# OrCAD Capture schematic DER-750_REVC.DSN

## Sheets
1 PAGE2: size A
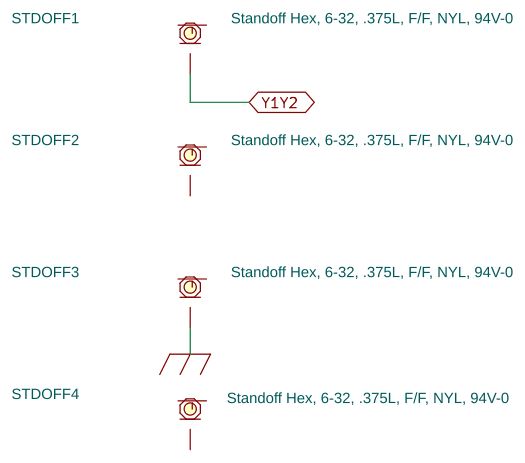
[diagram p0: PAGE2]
2 PAGE1: size Custom
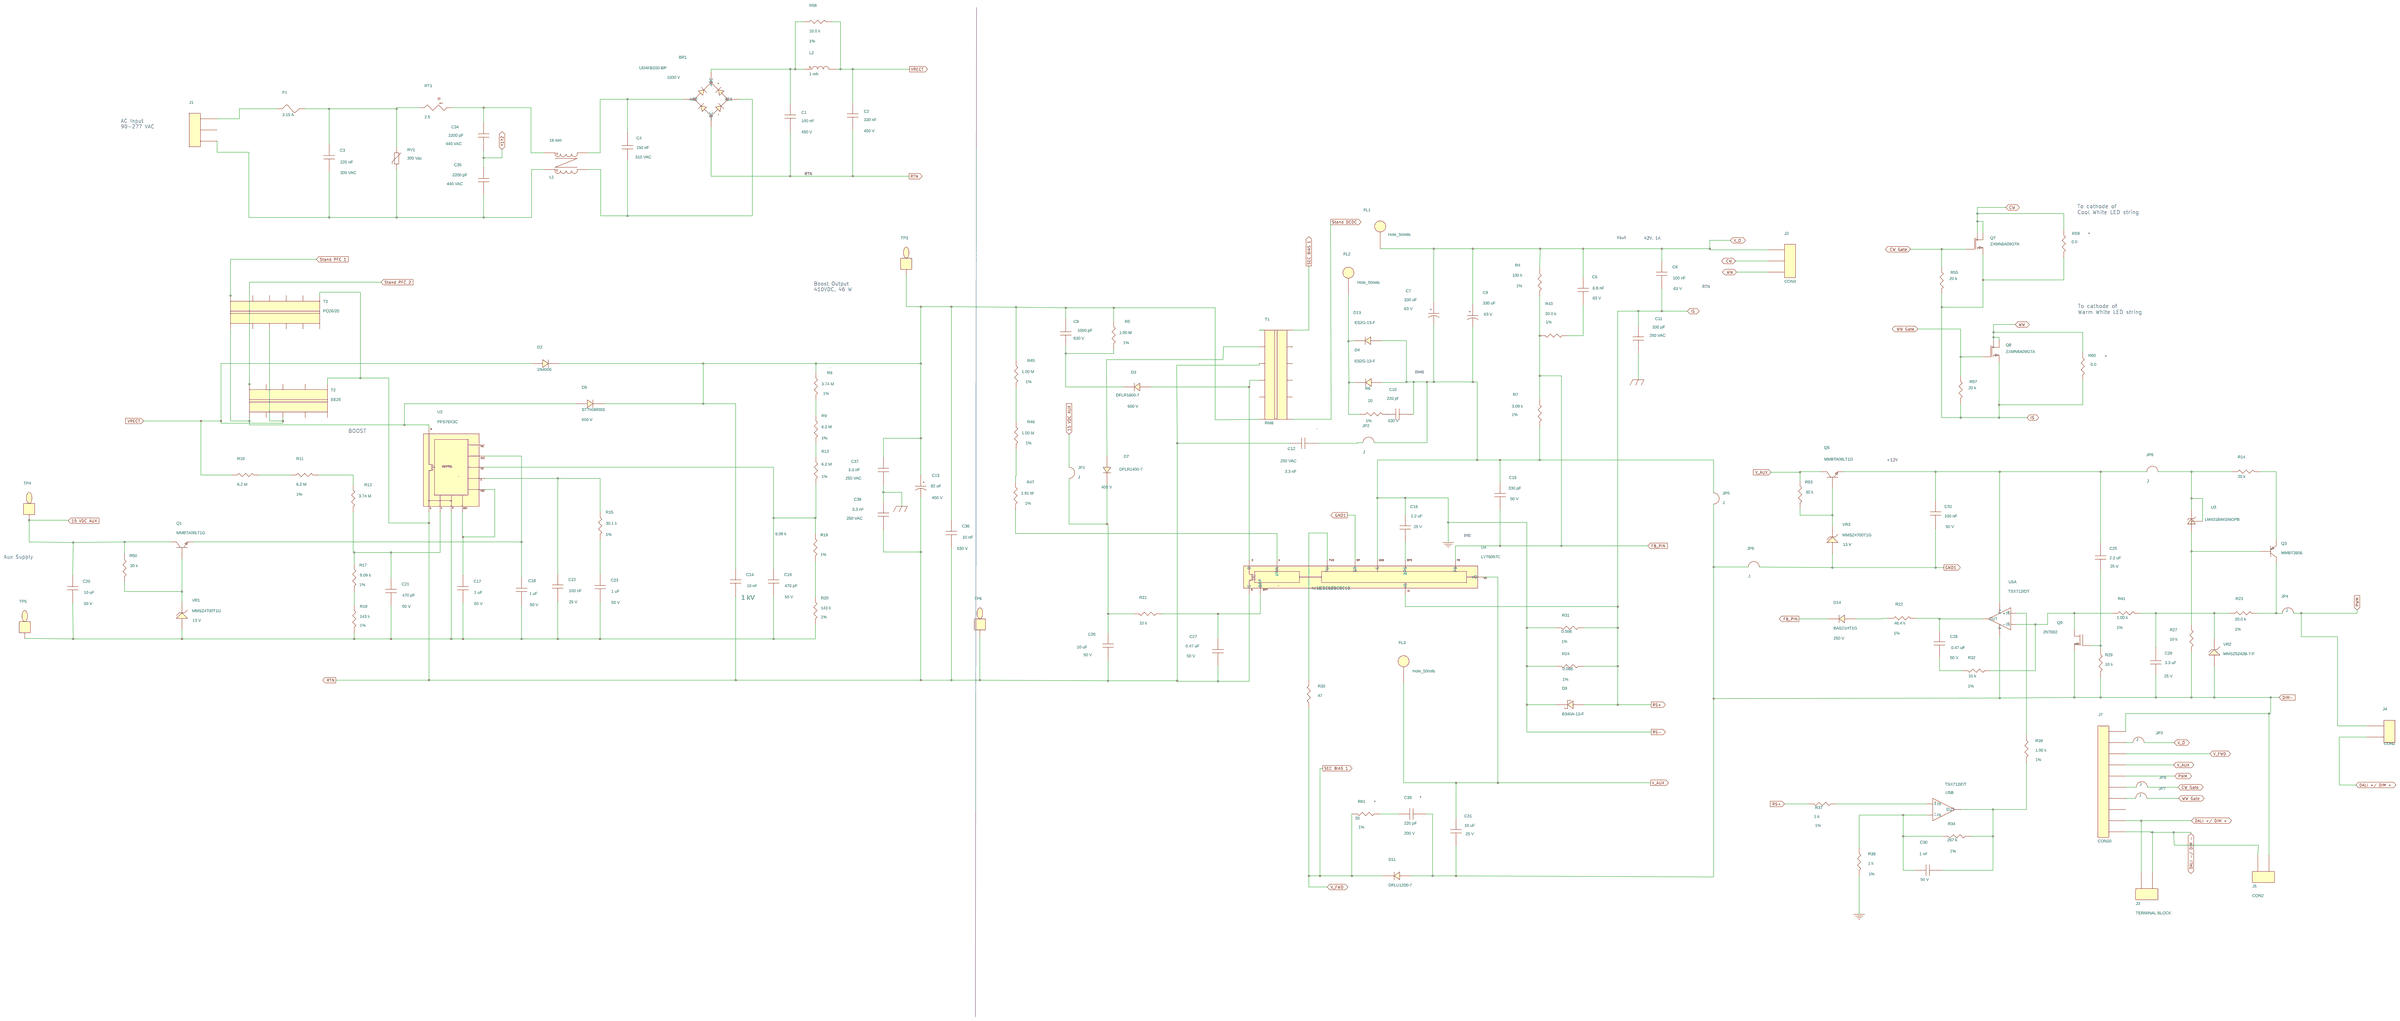
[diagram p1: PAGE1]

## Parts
sheet PAGE1
BR1  UD4KB100-BP  [pidaxbridgeD3K]
C1  100 nF  [pi_np_xcap_rad512x197x395d040]
C2  330 nF  [pi_np_caprad512x299ls394d040]
C3  220 nF  [pinpxcaprad710x315590046]
C4  150 nF  [pinpxcaprad720x240590040]
C5  6.8 nF  [pismc0603]
C6  100 nF  [pismc1206]
C7  330 uF  [pipolcapcyld400ls200040]
C8  330 uF  [pipolcapcyld400ls200040]
C9  1000 pF  [pismc1206]
C10  220 pf  [pismc1206]
C11  330 pF  [pinpycaprad470x210ls380040]
C12  3.3 nF  [pinpycaprad540x290ls400040]
C13  82 uF  [pipolcapclyd710ls300040]
C14  10 nF  [pi_np_cap250x200ls170d030]
C15  330 pF  [pismc0603]
C16  2.2 uF  [pismc1206]
C17  1 uF  [pismc0805]
C18  1 uF  [pismc0805]
C19  470 pF  [pismc0805]
C20  10 uF  [pismc1206]
C21  470 pF  [pismc0805]
C22  100 nF  [pismc0805]
C23  1 uF  [pismc0805]
C25  2.2 uF  [pismc0805]
C26  10 uF  [pismc1206]
C27  0.47 uF  [pismc0805]
C28  0.47 uF  [pismc0805]
C29  3.3 uF  [pismc0805]
C30  1 nF  [pismc0805]
C31  10 uF  [pismc1206]
C32  100 nF  [pismc0805]
C34  2200 pF  [pinpcaprad394x275394030]
C35  2200 pF  [pinpcaprad394x275394030]
C36  10 nF  [pismc1206]
C37  3.3 nF  [pinpycaprad540x290ls400040]
C38  3.3 nF  [pinpycaprad540x290ls400040]
C39  220 pF  [pismc0805]
D2  1N4006  [pidv200x110x040do41]
D3  DFLR1600-7  [pismddflr120012]
D4  ES2G-13-F  [pismdo214aa12]
D5  STTH3R06S  [pismdo214ab12]
D7  DFLR1400-7  [pismddflr120012]
D9  B340A-13-F  [pismdo214ac12]
D11  DFLU1200-7  [pismddflr120012]
D13  ES2G-13-F  [pismdo214aa12]
D14  BAS21HT1G  [pismsod323]
F1  3.15 A  [pi_rst_microfuse]
FL1  Hole_50mils  [pi_hole_50mil]
FL2  Hole_50mils  [pi_hole_50mil]
FL3  Hole_50mils  [pi_hole_50mil]
J1  TERMINAL BLOCK  [pi_term_block_3pin]
J2  CON3  [pi_hdr_3pin_phoenix_3p5ls100d]
J3  TERMINAL BLOCK  [pi_term_block_2pin_ls200]
J4  CON2  [pimolex2kkheader]
J5  CON2  [pimolex2kkheader]
J7  CON10  [pi_molex_10]
JP1  J  [pi_jumper200]
JP2  J  [pi_jumper300]
JP3  J  [pi_jumper300]
JP4  J  [pi_jumper300]
JP5  J  [pi_jumper1000]
JP6  J  [pi_jumper300]
JP7  J  [pi_jumper300]
JP8  J  [pi_jumper300]
JP9  J  [pi_jumper300]
L1  18 mH  [pi_ind_4p_690x512ls300x200d055]
L2  1 mh  [pi_choke_RL5480-5_d2]
Q1  MMBTA06LT1G  [pismsot23123_1]
Q3  MMBT3906  [pismsot23123_1]
Q5  2N7002  [pismsot23123_1]
Q6  MMBTA06LT1G  [pismsot23123_1]
Q7  ZXMN6A09GTA  [pismsot2231234]
Q8  ZXMN6A09GTA  [pismsot2231234]
R4  100 k  [pismr0805]
R5  1.00 M  [pismr1206]
R6  20  [pismr1206]
R7  3.09 k  [pismr0603]
R8  3.74 M  [pi14wvresd100ls100d030]
R9  6.2 M  [pismr1206]
R10  6.2 M  [pi14wvresd100ls100d030]
R11  6.2 M  [pismr1206]
R12  6.2 M  [pismr1206]
R13  3.74 M  [pismr1206]
R14  20 k  [pismr0603]
R15  30.1 k  [pismr0805]
R17  9.09 k  [pismr0805]
R18  143 k  [pismr0805]
R19  9.09 k  [pismr0805]
R20  143 k  [pismr0805]
R21  10 k  [pismr1206]
R22  46.4 k  [pismr1206]
R23  20.0 k  [pismr0805]
R24  0.068  [pismr1206]
R27  10 k  [pismr0805]
R29  10 k  [pismr0805]
R30  47  [pismr1206]
R31  0.068  [pismr1206]
R32  10 k  [pismr0805]
R34  267 k  [pismr0805]
R37  1 k  [pi14wvresd100ls100d030]
R38  1 k  [pi14wvresd100ls100d030]
R39  1.00 k  [pismr0805]
R41  1.00 k  [pismr0805]
R43  20.0 k  [pismr0805]
R45  1.00 M  [pismr1206]
R46  1.00 M  [pismr1206]
R47  1.91 M  [pismr1206]
R50  30 k  [pismr0805]
R53  30 k  [pismr0805]
R55  20 k  [pismr0805]
R57  20 k  [pismr0805]
R58  10.0 k  [pismr1206]
R59  0.0  [pismr0805]
R60  0.0  [pismr0805]
R61  20  [pismr1206]
RT1  2.5  [pi_rad150x300ls200d030]
RV1  300 Vac  [pidisc350x225ls240x140040]
T1  RM8  [pi_bobbin_rm8_12p]
T2  EE25  [pi_bobbin_ee25_10p]
T3  PQ26/20  [pi_bobbin_bpq26_20_12p]
TP3  CON1  [pitpkeystone125x125]
TP4  CON1  [pitpkeystone125x125]
TP5  CON1  [pitpkeystone125x125]
TP6  CON1  [pitpkeystone125x125]
U2  PFS76X3C  [PI_IC_INSOP24B]
U3  LM431BIM3/NOPB  [pismsot23123]
U4  LYT6067C  [pi_ic_insop_24d]
U5  TSX712IDT  [pismso8]  (sections A,B)
VR1  MMSZ4700T1G  [pi_sm_sod-123_12]
VR2  MMSZ5242B-7-F  [pi_sm_sod-123_12]
VR3  MMSZ4700T1G  [pi_sm_sod-123_12]
sheet PAGE2
STDOFF1  Standoff Hex, 6-32, .375L, F/F, NYL, 94V-0  [pi_standoff_6_32]
STDOFF2  Standoff Hex, 6-32, .375L, F/F, NYL, 94V-0  [pi_standoff_6_32]
STDOFF3  Standoff Hex, 6-32, .375L, F/F, NYL, 94V-0  [pi_standoff_6_32]
STDOFF4  Standoff Hex, 6-32, .375L, F/F, NYL, 94V-0  [pi_standoff_6_32]

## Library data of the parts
BR1 = DISCRETE_BRIDGE_+~~-: ALT_SYMBOLS: pidaxbridgeD3K_horz; Disp_Voltage: 1000 V; FPLIST: pidaxbridgeD3K,pidaxbridgeD3K_horz; Part Number: 15-01213-00
C1 = CAP_NP: Disp_Voltage: 450 V; Part Number: 20-01140-00; Voltage: 450 V
C2 = CAP_NP: ALT_SYMBOLS: pi_np_caprad512x299ls394d040_h; Disp_Voltage: 450 V; FPLIST: pi_np_caprad512x299ls394d040,pi_np_caprad512x299ls394d040_h; Part Number: 20-00973-00; Voltage: 450 V
C3 = CAP_NP: Disp_Voltage: 300 VAC; Part Number: 20-00730-00; Voltage: 300 VAC
C4 = CAP_NP: Disp_Voltage: 310 VAC; Part Number: 20-01052-00; Voltage: 310 VAC
C5 = CAP_NP: Disp_Voltage: 63 V; Part Number: 20-08888-00; Voltage: 50 V
C6 = CAP_NP: Disp_Voltage: 63 V; Part Number: 20-08738-00; Voltage: 50 V
C7 C8 = CAP_POL: COMPGROUP: 3; Disp_Voltage: 63 V; FPLIST: pipolcapcyld400ls200040,pipolcapcylD10mLS5mH22m040H; Part Number: 20-09012-00; Voltage: 50 V
C9 = CAP_NP: Disp_Voltage: 630 V; Part Number: 20-08616-00; Voltage: 630 V
C10 = CAP_NP: Disp_Voltage: 630 V; PCB Editor PCBFP: pismc0603; Part Number: 20-01036-00; Voltage: 630 V
C11 = CAP_NP: Disp_Voltage: 250 VAC; Part Number: 20-00373-00; Voltage: 250 VAC
C12 = CAP_NP: ALT_SYMBOLS: pinpycaprad540x290ls400040h; COMPGROUP: 3; Disp_Voltage: 250 VAC; FPLIST: pinpycaprad540x290ls400040,pinpycaprad540x290ls400040h; Part Number: 20-00377-00; Voltage: 250 VAC
C13 = CAP_POL: ALT_SYMBOLS: pi_cap_cly_d710_ls300_040_1035h; Disp_Voltage: 450 V; FPLIST: pipolcapclyd710ls300040,pi_cap_cly_d710_ls300_040_1035h; Part Number: 20-00523-00; Voltage: 450 V
C14 = CAP_NP: Disp_Voltage: 1 kV; Part Number: 20-00894-00; Voltage: 1 kV
C15 = CAP_NP: Disp_Voltage: 50 V; Part Number: 20-08676-00; Voltage: 50 V
C16 = CAP_NP: Disp_Voltage: 25 V; Part Number: 20-01034-00; Voltage: 25 V
C17 C18 C23 = CAP_NP: Disp_Voltage: 50 V; Part Number: 20-09156-00; Voltage: 50 V
C19 C21 = CAP_NP: Disp_Voltage: 50 V; Part Number: 20-00205-00; Voltage: 50 V
C20 C26 = CAP_NP: ALT_SYMBOLS: pismc1206_1; Disp_Voltage: 50 V; FPLIST: pismc1206,pismc1206_1; Part Number: 20-08995-00; Voltage: 50 V
C22 = CAP_NP: Disp_Voltage: 25 V; Part Number: 20-08599-00; Voltage: 25 V
C25 = CAP_NP: Disp_Voltage: 25 V; Part Number: 20-08603-00; Voltage: 25 V
C27 C28 = CAP_NP: Disp_Voltage: 50 V; Part Number: 20-09197-00; Voltage: 50 V
C29 = CAP_NP: Disp_Voltage: 25 V; Part Number: 20-01041-00; Voltage: 25 V
C30 = CAP_NP: Disp_Voltage: 50 V; Part Number: 20-08750-00; Voltage: 50 V
C31 = CAP_NP: Disp_Voltage: 25 V; Part Number: 20-08608-00; Voltage: 25 V
C32 = CAP_NP: Disp_Voltage: 50 V; Part Number: 20-00904-00; Voltage: 50 V
C34 C35 = CAP_NP: ALT_SYMBOLS: pinpycaprad500x220ls400040; Disp_Voltage: 440 VAC; FPLIST: pinpcaprad394x275394030,pinpycaprad500x220ls400040; Part Number: 20-09196-00; Voltage: 440 VAC
C36 = CAP_NP: Disp_Voltage: 630 V; Part Number: 20-00939-00; Voltage: 630 V
C37 C38 = CAP_NP: ALT_SYMBOLS: pinpycaprad540x290ls400040h; Disp_Voltage: 250 VAC; FPLIST: pinpycaprad540x290ls400040,pinpycaprad540x290ls400040h; Part Number: 20-00377-00; Voltage: 250 VAC
C39 = CAP_NP: Disp_Voltage: 200 V; Part Number: 20-09094-00; Voltage: 200 V
D2 = DIODE: ALT_SYMBOLS: pidax475x125040do41,pidv200x110x040do41wbead,pidax390x125040do41; FPLIST: pidv200x110x040do41,pidax475x125040do41,pidv200x110x040do41wbead,pidax390x125040do41; Part Number: 15-00629-00
D3 = DIODE: Disp_Voltage: 600 V; Part Number: 15-00826-00
D4 D13 = DIODE: Part Number: 15-01075-00
D5 = DIODE: Disp_Voltage: 600 V; Part Number: 15-00827-00
D7 = DIODE: COMPGROUP: 1; Disp_Voltage: 400 V; Part Number: 15-01310-00
D9 = DIODE_SCHOTTKY: Part Number: 15-01172-00
D11 = DIODE: Part Number: 15-01043-00
D14 = DIODE: ALT_SYMBOLS: pismsod323_1; Disp_Voltage: 250 V; FPLIST: pismsod323,pismsod323_1; Part Number: 15-01247-00
F1 = FUSE: ALT_SYMBOLS: pirstmicrofusehoz; FPLIST: pi_rst_microfuse,pirstmicrofusehoz; Part Number: 40-00020-00
FL1-FL3 = FlyingLead: Part Number: 35-00283-00
J1 = CON3: Part Number: 35-00175-00
J2 = CON3: Part Number: 35-00463-00
J3 = CON2: Part Number: 35-00277-00
J4 J5 = CON2: Part Number: 35-00077-00
J7 = CON10: Part Number: 35-00014-00
JP1 = JUMPER_1: Part Number: 65-00119-00
JP2-JP4 JP6-JP9 = JUMPER_1: Part Number: 65-00120-00
JP5 = JUMPER_1: Part Number: 65-00127-00
L1 = CMC__4P_12_43: ALT_SYMBOLS: pi_4p_700x400d055_horiz; FPLIST: pi_ind_4p_690x512ls300x200d055,pi_4p_700x400d055_horiz; Part Number: 30-04100-00
L2 = INDUCTOR_dot2: ALT_SYMBOLS: pi_choke_RL5480-5H_d2; FPLIST: pi_choke_RL5480-5_d2,pi_choke_RL5480-5H_d2; Part Number: 30-00318-00
Q1 Q6 = NPN_BEC: Part Number: 55-00072-00
Q3 = PNP_BEC: Part Number: 55-00049-00
Q5 = FET_N_GSD: Part Number: 50-00103-00
Q7 Q8 = FET_N_GDSD: Part Number: 50-00248-00
R4 = R: Disp_Tol: 1%; Part Number: 05-00780-00
R5 R45 R46 = R: Disp_Tol: 1%; Part Number: 05-03149-00
R6 R61 = R: Disp_Tol: 1%; Part Number: 05-00030-00
R7 = R: Disp_Tol: 1%; Part Number: 05-01125-00
R8 = R: ALT_SYMBOLS: pi14wvresd100ls200d030,pi14wresd100ls400d030,pi14wresd100ls500d030; Disp_Tol: 1%; FPLIST: pi14wvresd100ls100d030,pi14wvresd100ls200d030,pi14wresd100ls400d030,pi14wresd100ls500d030; Part Number: 05-05566-00
R9 R11 R12 = R: Disp_Tol: 1%; Part Number: 05-05567-00
R10 = R: ALT_SYMBOLS: pi14wvresd100ls200d030,pi14wresd100ls400d030,pi14wresd100ls500d030; FPLIST: pi14wvresd100ls100d030,pi14wvresd100ls200d030,pi14wresd100ls400d030,pi14wresd100ls500d030; Part Number: 05-03122-00
R13 = R: Part Number: 05-05572-00
R14 = R: Part Number: 05-01719-00
R15 = R: Disp_Tol: 1%; Part Number: 05-00730-00
R17 R19 = R: Disp_Tol: 1%; Part Number: 05-03397-00
R18 R20 = R: Disp_Tol: 1%; Part Number: 05-00795-00
R21 = R: Part Number: 05-01376-00
R22 = R: Disp_Tol: 1%; Part Number: 05-00353-00
R23 R43 = R: Disp_Tol: 1%; Part Number: 05-00713-00
R24 R31 = R: Disp_Tol: 1%; Part Number: 05-06499-00
R27 R29 = R: Part Number: 05-01543-00
R30 = R: Part Number: 05-01320-00
R32 = R: Disp_Tol: 1%; Part Number: 05-00684-00
R34 = R: Disp_Tol: 1%; Part Number: 05-00821-00
R37 R38 = R: ALT_SYMBOLS: pi14wvresd100ls200d030,pi14wresd100ls400d030,pi14wresd100ls500d030; Disp_Tol: 1%; FPLIST: pi14wvresd100ls100d030,pi14wvresd100ls200d030,pi14wresd100ls400d030,pi14wresd100ls500d030; Part Number: 05-01976-00
R39 R41 = R: Disp_Tol: 1%; Part Number: 05-03310-00
R47 = R: Disp_Tol: 1%; Part Number: 05-05409-00
R50 R53 = R: Part Number: 05-01554-00
R55 R57 = R: Part Number: 05-01550-00
R58 = R: Disp_Tol: 1%; Part Number: 05-00289-00
R59 R60 = R: ALT_SYMBOLS: pismr0805_1; FPLIST: pismr0805,pismr0805_1; Part Number: 05-03159-00
RT1 = THERMISTOR: ALT_SYMBOLS: pirad400x300ls200040_h; FPLIST: pi_rad150x300ls200d030,pirad400x300ls200040_h; Part Number: 90-00040-00
RV1 = VARISTOR: Part Number: 85-00031-00
T1 = BRM8_12P_GENERIC: ALT_SYMBOLS: pi_bobbin_rm8_12p_inline_clp; FPLIST: pi_bobbin_rm8_12p,pi_bobbin_rm8_12p_inline_clp; Part Number: 25-00041-00
T2 = BEE25_10P_GENERIC: Part Number: 25-00015-00
T3 = BPQ26_20_12P_GENERIC: Part Number: 25-00025-00
TP3 TP4 = TESTPOINT: Part Number: 35-00042-00
TP5 TP6 = TESTPOINT: Part Number: 35-00044-00
U2 = DEV_HiperPFS7_inSOP: Part Number: 10-01067-00
U3 = TL431_SOT-23_CAR: Part Number: 45-00232-00
U4 = LYT6: Part Number: 10-01080-00
U5 = TSX712IDT: Part Number: 45-00514-00
VR1 VR3 = DIODE_ZENER: Disp_Voltage: 13 V; Part Number: 15-01046-00
VR2 = DIODE_ZENER: Part Number: 15-01090-00
STDOFF1-STDOFF4 = STDOFF_HEX_6-32: Part Number: 76-00032-00

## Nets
GND: C7.2 C8.2 C10.2 C15.1 C16.1 D4.2 D9.1 D13.2 JP2.2 JP5.1 R7.2 R24.2 R31.2 R38.2 U4.2(G)
GND1: C32.2 JP6.2 U4.5(SR) VR3.2
GND_EARTH: C11.2 C37.2 C38.1 STDOFF3.1
15 VDC AUX: C20.1 JP1.1 Q1.3(COLLECTOR) R50.1 TP4.1
CW: J2.2 Q7.2(D1) Q7.4(D2) R59.1
CW Gate: JP9.2 Q7.1(G) R55.1
DALI +/ DIM +: J3.2 J4.2 J7.2
DALI -/ DIM -: J3.1 J5.2 J7.1
DIM-: C29.1 C31.2 C39.2 D11.2 J5.1 J7.10 JP5.2 JP6.1 Q5.2(S) R27.2 R29.2 U5.4(V-) VR2.2
FB_PIN: C15.2 D14.1 R4.2 R7.1 R43.2 U4.3(FB)
IS: C6.2 C11.1 D9.2 Q7.3(S) Q8.3(S) R24.1 R31.1 R37.2 R55.2 R57.2 R59.2 R60.2 U4.1(IS)
NC8: U4.8(NC8)
NC9: U2.9(NC9) U4.9(NC9)
NC10: U2.10(NC10) U4.10(NC10)
NC11: U2.11(NC11) U4.11(NC11)
NC12: U2.12(NC12) U4.12(NC12)
NC13: U2.13(NC13)
NC14: U2.14(NC14)
NC15: U2.15(NC15) U4.15(nc15)
PWM: J4.1 J7.6 JP4.2
RTN: BR1.4(-DC) C1.2 C2.2 C12.1 C13.2 C14.2 C26.2 C27.2 C36.2 C38.2 T1.4 T2.6 T3.7 TP6.1 U2.24(S) U4.16(S)
SEC BIAS 1: D11.1 J7.8 R30.1 R61.2 T1.7
Stand DCDC: T1.12
Stand PFC 1: T3.12
Stand PFC 2: T2.10
V_AUX: C31.1 FL3.1 J7.7 Q6.3(COLLECTOR) R53.1 U4.6(VO)
V_O: C5.1 C6.1 C7.1 C8.1 FL1.1 J2.1 JP3.2 R4.1
VRECT: C2.1 D2.2 L2.1 R10.1 R58.2 T2.3 T3.3
WW: J2.3 Q8.2(D1) Q8.4(D2) R60.1
WW Gate: JP7.2 Q8.1(G) R57.1
Y1Y2: C34.2 C35.1 STDOFF1.1
N11473952: BR1.1(+DC) C1.1 L2.2 R58.1
N11474046: F1.1 J1.3
N11474074: C3.1 F1.2 RT1.1 RV1.1
N11474232: C3.2 C35.2 J1.1 L1.4 RV1.2
N11475153: C9.2 C13.1 C14.1 C36.1 C37.1 D2.1 D5.1 R5.1 R8.1 R45.1 T1.1 TP3.1
N11476179: D5.2 T2.1 T3.1 U2.16(D)
N11479125: C18.1 Q1.2(EMITTER) U2.1(VCC)
N11479543: C19.1 R12.1 R19.1 U2.6(FB)
N11479547: C22.1 R15.1 U2.5(C)
N11479611: C23.1 R15.2
N11479651: C17.2 C18.2 C19.2 C20.2 C21.2 C22.2 C23.2 R18.2 R20.2 TP5.1 U2.2(G) VR1.2
N11480020: C21.1 R13.2 R17.1 U2.4(V)
N11480864: R10.2 R11.1
N11480868: R11.2 R13.1
N11481429: C17.1 U2.3(REF) U2.8(PGT)
N11482333: R9.2 R12.2
N11498937: D4.1 D13.1 FL2.1 R6.2
N11498945: C9.1 D3.1 R5.2
N11499175: C10.1 R6.1
N11499187: D7.2 T1.5
N11499225: D3.2 T1.3 U4.24(D)
N11499449: C26.1 D7.1 JP1.2 R21.1
N11499609: R30.2 U4.7(FW)
N11499647: R47.2 U4.13(VPIN)
N11499655: C16.2 U4.4(BPS)
N11499799: C27.1 R21.2 U4.14(BPP)
N11939314: R19.2 R20.1
N11939723: R17.2 R18.1
N11948429: R45.2 R46.1
N11948437: R46.2 R47.1
N12022540: C12.2 JP2.1
N12100407: C25.2 C32.1 JP8.1 Q6.2(EMITTER) U5.8(V+)
N12100435: JP8.2 R14.1 U3.1(C) U3.3(VREF)
N12100443: Q3.2(EMITTER) R14.2
N12100467: Q6.1(BASE) R53.2 VR3.1
N12100553: Q3.1(BASE) R27.1 U3.2(A)
N12100613: JP4.1 Q3.3(COLLECTOR) R23.2
N12100617: C25.1 Q5.1(G) R29.1
N12100771: R39.1 U5.3(+IN)
N12100779: Q5.3(D) R32.1 R41.1 U5.2(-IN)
N12100795: C29.2 R23.1 R41.2 VR2.1
N12100835: D14.2 R22.1
N12100839: C28.1 R22.2 U5.1(OUT)
N12100987: C28.2 R32.2
N12101111: C30.2 R34.1 R39.2 U5.7(OUT)
N12101185: R37.1 U5.5(+IN)
N12101201: C30.1 R34.2 R38.1 U5.6(-IN)
N12102647: Q1.1(BASE) R50.2 VR1.1
N12107790: J7.9 JP3.1
N12159127: R8.2 R9.1
N12184871: C5.2 R43.1
N12192768: C39.1 R61.1
N12236438: BR1.3(AC2) C4.2 L1.2
N12236447: C34.1 L1.1 RT1.2
N12236503: BR1.2(AC1) C4.1 L1.3
N12238576: J7.5 JP9.1
N12238603: J7.4 JP7.1

Not connected (* = marked no-connect by the designer): J1 2; J7 3; STDOFF2 1; STDOFF4 1; T1 2 6 8 9 10 11; T2 2 4 5 7 8 9; T3 2 4 5 6 8 9 10 11; U2 7(PG)

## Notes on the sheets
sheet 2
- AC Input
  90-277 VAC
- To cathode of
  Cool White LED string
- *
- Vout
- 42V, 1A
- Boost Output
  410VDC, 46 W
- RTN
- To cathode of
  Warm White LED string
- *
- (GND)
- BOOST
- +12V
- (VO)
- Aux Supply
- *
- *
